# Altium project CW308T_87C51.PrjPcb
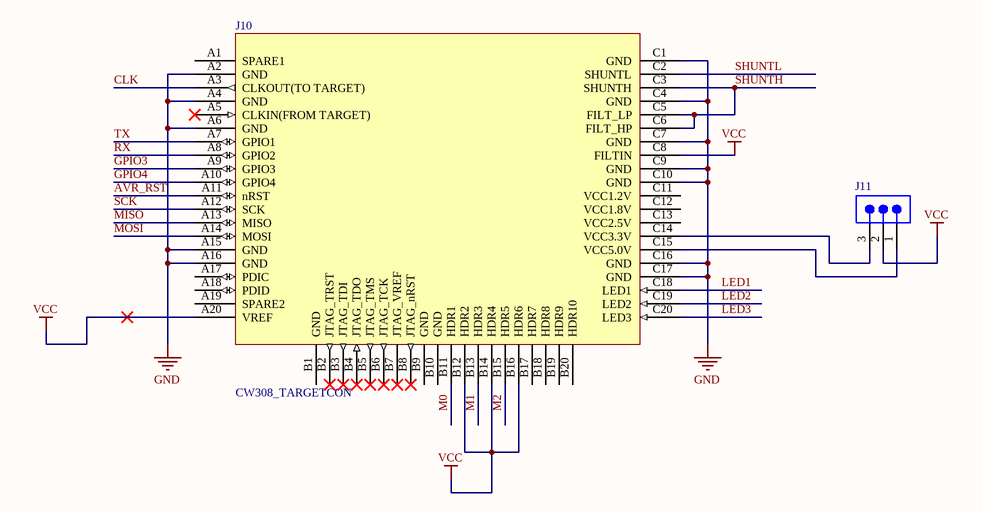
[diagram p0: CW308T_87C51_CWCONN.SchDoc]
2 sheets, 35 parts. Net scope: global (net labels, ports and power ports of the same name join across sheets).
Board file: CW308T_87C51.PcbDoc
Sheets:
  CW308T_87C51_CWCONN.SchDoc
  CW308T_87C51_CPU.SchDoc

## Sheet CW308T_87C51_CWCONN.SchDoc
size A4

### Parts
J10  CW308_TARGETCON  [CW308_TBOARD_CONN]
J11  68000-203HLF  [SMTC-TSW-103-07-X-S]  (value not drawn)

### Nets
GND: J10.A2(GND) J10.A4(GND) J10.A6(GND) J10.A15(GND) J10.A16(GND) J10.C1(GND) J10.C4(GND) J10.C7(GND) J10.C9(GND) J10.C10(GND) J10.C16(GND) J10.C17(GND)
VCC: J10.A20(VREF) J10.B12(HDR2) J10.B14(HDR4) J10.B16(HDR6) J10.C8(FILTIN) J11.2
AVR_RST: J10.A11(nRST)
CLK: J10.A3(CLKOUT(TO_TARGET))
GPIO3: J10.A9(GPIO3)
GPIO4: J10.A10(GPIO4)
LED1: J10.C18(LED1)
LED2: J10.C19(LED2)
LED3: J10.C20(LED3)
M0: J10.B11(HDR1)
M1: J10.B13(HDR3)
M2: J10.B15(HDR5)
MISO: J10.A13(MISO)
MOSI: J10.A14(MOSI)
RX: J10.A8(GPIO2)
SCK: J10.A12(SCK)
SHUNTH: J10.C3(SHUNTH) J10.C5(FILT_LP) J10.C6(FILT_HP)
SHUNTL: J10.C2(SHUNTL)
TX: J10.A7(GPIO1)
NetJ10_C14: J10.C14(VCC3.3V) J11.3
NetJ10_C15: J10.C15(VCC5.0V) J11.1

Not connected (* = marked no-connect by the designer): J10 A1(SPARE1) A5(CLKIN(FROM_TARGET))* A17(PDIC) A18(PDID) A19(SPARE2) B1(GND) B2(JTAG_TRST)* B3(JTAG_TDI)* B4(JTAG_TDO)* B5(JTAG_TMS)* B6(JTAG_TCK)* B7(JTAG_VREF)* B8(JTAG_nRST)* B9(GND) B10(GND) B17(HDR7) B18(HDR8) B19(HDR9) B20(HDR10) C11(VCC1.2V) C12(VCC1.8V) C13(VCC2.5V)

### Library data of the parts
J10 = CW308_TBOARD: CW308 "Standard" Target Board Connector
J11 = CMP-1024-00333-1: Manufacturer: Samtec; Pitch: 2.54 mm

## Sheet CW308T_87C51_CPU.SchDoc
size A4
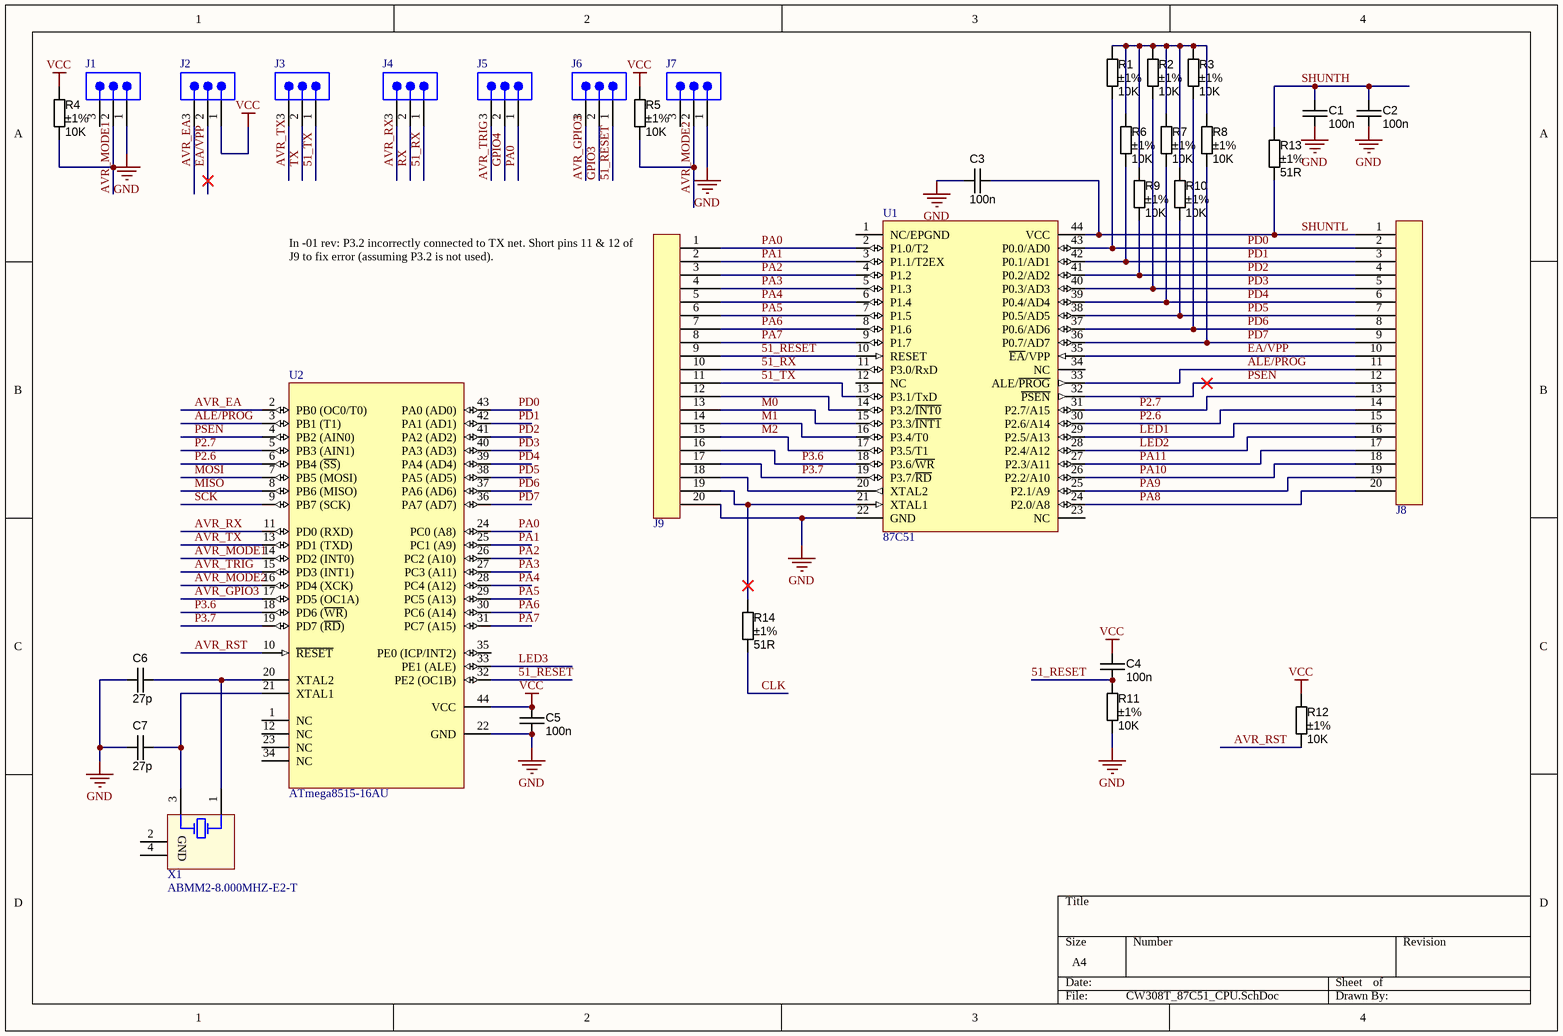
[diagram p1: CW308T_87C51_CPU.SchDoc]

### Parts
C1  value 100n  [CAPC1608X90N]  (hidden comment: approved sub OK)
C2  value 100n  [CAPC1608X90N]  (hidden comment: approved sub OK)
C3  value 100n  [CAPC1608X90N]  (hidden comment: approved sub OK)
C4  value 100n  [CAPC1608X90N]  (hidden comment: approved sub OK)
C5  value 100n  [CAPC1608X90N]  (hidden comment: approved sub OK)
C6  27p  [CAPC1608X90N]
C7  27p  [CAPC1608X90N]
J1  68000-203HLF  [SMTC-TSW-103-07-X-S]  (value not drawn)
J2  68000-203HLF  [SMTC-TSW-103-07-X-S]  (value not drawn)
J3  68000-203HLF  [SMTC-TSW-103-07-X-S]  (value not drawn)
J4  68000-203HLF  [SMTC-TSW-103-07-X-S]  (value not drawn)
J5  68000-203HLF  [SMTC-TSW-103-07-X-S]  (value not drawn)
J6  68000-203HLF  [SMTC-TSW-103-07-X-S]  (value not drawn)
J7  68000-203HLF  [SMTC-TSW-103-07-X-S]  (value not drawn)
J8  20-Pin Header  [801-87-020-10-001101]  (value not drawn)
J9  20-Pin Header  [801-87-020-10-001101]  (value not drawn)
R1  value 10K  Tolerance: ±1%  [RESC1608X55N]  (hidden comment: Thick Film)
R2  value 10K  Tolerance: ±1%  [RESC1608X55N]  (hidden comment: Thick Film)
R3  value 10K  Tolerance: ±1%  [RESC1608X55N]  (hidden comment: Thick Film)
R4  value 10K  Tolerance: ±1%  [RESC1608X55N]  (hidden comment: Thick Film)
R5  value 10K  Tolerance: ±1%  [RESC1608X55N]  (hidden comment: Thick Film)
R6  value 10K  Tolerance: ±1%  [RESC1608X55N]  (hidden comment: Thick Film)
R7  value 10K  Tolerance: ±1%  [RESC1608X55N]  (hidden comment: Thick Film)
R8  value 10K  Tolerance: ±1%  [RESC1608X55N]  (hidden comment: Thick Film)
R9  value 10K  Tolerance: ±1%  [RESC1608X55N]  (hidden comment: Thick Film)
R10  value 10K  Tolerance: ±1%  [RESC1608X55N]  (hidden comment: Thick Film)
R11  value 10K  Tolerance: ±1%  [RESC1608X55N]  (hidden comment: Thick Film)
R12  value 10K  Tolerance: ±1%  [RESC1608X55N]  (hidden comment: Thick Film)
R13  value 51R  Tolerance: ±1%  [RESC1608X55N]  (hidden comment: Thick Film)
R14  value 51R  Tolerance: ±1%  [RESC1608X55N]  (hidden comment: Thick Film)
U1  87C51  [PLCC44_SOCKET]
U2  ATmega8515-16AU  [44A_N]
X1  ABMM2-8.000MHZ-E2-T  [ABRA-ABMM2-4_V]

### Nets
GND: C1.2 C2.2 C3.1 C5.2 C6.1 C7.1 J1.1 J7.1 J9.20 R11.2 U1.22(GND) U2.22(GND)
VCC: C4.1 C5.1 J2.1 R4.1 R5.2 R12.1 U2.44(VCC)
51_RESET: C4.2 J6.1 J9.9 R11.1 U1.10(RESET) U2.32(PE2_(OC1B))
51_RX: J4.1 J9.10 U1.11(P3.0/RxD)
51_TX: J3.1 J9.11 U1.13(P3.1/TxD)
ALE/PROG: J8.11 U1.33(ALE/~{PROG}) U2.3(PB1_(T1))
AVR_EA: J2.3 U2.2(PB0_(OC0/T0))
AVR_GPIO3: J6.3 U2.17(PD5_(OC1A))
AVR_MODE1: J1.2 R4.2 U2.14(PD2_(INT0))
AVR_MODE2: J7.2 R5.1 U2.16(PD4_(XCK))
AVR_RST: R12.2 U2.10(~{RESET})
AVR_RX: J4.3 U2.11(PD0_(RXD))
AVR_TRIG: J5.3 U2.15(PD3_(INT1))
AVR_TX: J3.3 U2.13(PD1_(TXD))
CLK: R14.2
EA/VPP: J2.2 J8.10 U1.35(~{EA}/VPP)
GPIO3: J6.2
GPIO4: J5.2
LED1: J8.15 U1.29(P2.5/A13)
LED2: J8.16 U1.28(P2.4/A12)
LED3: U2.33(PE1_(ALE))
M0: J9.13 U1.15(P3.3/~{INT1})
M1: J9.14 U1.16(P3.4/T0)
M2: J9.15 U1.17(P3.5/T1)
MISO: U2.8(PB6_(MISO))
MOSI: U2.7(PB5_(MOSI))
P2.6: J8.14 U1.30(P2.6/A14) U2.6(PB4_(~{SS}))
P2.7: J8.13 U1.31(P2.7/A15) U2.5(PB3_(AIN1))
P3.6: J9.16 U1.18(P3.6/~{WR}) U2.18(PD6_(~{WR}))
P3.7: J9.17 U1.19(P3.7/~{RD}) U2.19(PD7_(~{RD}))
PA0: J5.1 J9.1 U1.2(P1.0/T2) U2.24(PC0_(A8))
PA1: J9.2 U1.3(P1.1/T2EX) U2.25(PC1_(A9))
PA2: J9.3 U1.4(P1.2) U2.26(PC2_(A10))
PA3: J9.4 U1.5(P1.3) U2.27(PC3_(A11))
PA4: J9.5 U1.6(P1.4) U2.28(PC4_(A12))
PA5: J9.6 U1.7(P1.5) U2.29(PC5_(A13))
PA6: J9.7 U1.8(P1.6) U2.30(PC6_(A14))
PA7: J9.8 U1.9(P1.7) U2.31(PC7_(A15))
PA8: J8.20 U1.24(P2.0/A8)
PA9: J8.19 U1.25(P2.1/A9)
PA10: J8.18 U1.26(P2.2/A10)
PA11: J8.17 U1.27(P2.3/A11)
PD0: J8.2 R1.2 U1.43(P0.0/AD0) U2.43(PA0_(AD0))
PD1: J8.3 R6.2 U1.42(P0.1/AD1) U2.42(PA1_(AD1))
PD2: J8.4 R9.2 U1.41(P0.2/AD2) U2.41(PA2_(AD2))
PD3: J8.5 R2.2 U1.40(P0.3/AD3) U2.40(PA3_(AD3))
PD4: J8.6 R7.2 U1.39(P0.4/AD4) U2.39(PA4_(AD4))
PD5: J8.7 R10.2 U1.38(P0.5/AD5) U2.38(PA5_(AD5))
PD6: J8.8 R3.2 U1.37(P0.6/AD6) U2.37(PA6_(AD6))
PD7: J8.9 R8.2 U1.36(P0.7/AD7) U2.36(PA7_(AD7))
PSEN: J8.12 U1.32(~{PSEN}) U2.4(PB2_(AIN0))
RX: J4.2
SCK: U2.9(PB7_(SCK))
SHUNTH: C1.1 C2.1 R13.1
SHUNTL: C3.2 J8.1 R13.2 U1.44(VCC)
TX: J3.2
NetC6_2: C6.2 U2.20(XTAL2) X1.1(X1)
NetC7_2: C7.2 U2.21(XTAL1) X1.3(X2)
NetJ9_12: J9.12 U1.14(P3.2/~{INT0})
NetJ9_18: J9.18 U1.20(XTAL2)
NetJ9_19: J9.19 R14.1 U1.21(XTAL1)
NetR1_1: R1.1 R2.1 R3.1 R6.1 R7.1 R8.1 R9.1 R10.1

Not connected (* = marked no-connect by the designer): J1 3; J7 3; U1 1(NC/EPGND) 12(NC) 23(NC) 34(NC); U2 1(NC) 12(NC) 23(NC) 34(NC) 35(PE0_(ICP/INT2)); X1 2(GND) 4(GND)

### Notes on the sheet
- (near J9) In -01 rev: P3.2 incorrectly connected to TX net. Short pins 11 & 12 of J9 to fix error (assuming P3.2 is not used).

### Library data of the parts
C1-C5 = CAPC_100n_0603_X7R_50V_10%: Capacitor SMD Cer 100nF 10% 50V X7R 0603; Manufacturer 1: AVX Corporation; Manufacturer Part Number 1: 06035C104KAT2A; Ratings: 50V; X7R; Material: ceramic; SCDType: spec
C6 C7 = CAPC_27p_0603_NP0_100V_1%: Capacitor SMD Cer 27pF 1% 100V NP0 0603; Manufacturer 1: AVX Corporation; Manufacturer Part Number 1: 06031A270FAT2A; Ratings: 100V; NP0; SCDType: undef
J1-J7 = CMP-1024-00333-1: Manufacturer: Samtec; Pitch: 2.54 mm
J8 J9 = 801-87-020-10-001101: 1x20 Header, Machined; Manufacture 1: Preci-Dip SA
R1-R12 = RES_10K_0603_1%: Resistor SMD chip 10k Ohm 0.1W 1% 0603; Manufacturer 1: Yageo; Manufacturer Part Number 1: RC0603FR-0710KL; Ratings: 1/10W; SCDType: spec
R13 R14 = RES_51R_0603_1%: Resistor SMD chip 51 Ohm 0.1W 1% 0603; Manufacturer 1: Yageo; Manufacturer Part Number 1: RC0603FR-0751RL; Ratings: 1/10 W; SCDType: spec
U2 = CMP-0095-00300-2: 8-bit AVR Microcontroller, 8KB Flash, 512 Bytes EEPROM, 512 Bytes SRAM, 4.5-5.5V, 44-pin TQFP, Industrial Grade (-40°C to 85°C)
X1 = CMP-0277-00003-1: Ceramic Surface Mount Low Profile Quartz Crystal, 8 MHz, -20 to 70 degC, 4-Pin 6 x 3.6 x 1.2 mm SMD, RoHS, 1000pcs / Reel; Manufacturer: Abracon; ESR: 72 Ohm Max.; Frequency: 8 MHz; Shunt Capacitance C0: 7 pF Max.; Load Capacitance CL: 18 pF Typ.

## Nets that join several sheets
GND: CW308T_87C51_CWCONN (12 pins), CW308T_87C51_CPU (12 pins)
VCC: CW308T_87C51_CWCONN (6 pins), CW308T_87C51_CPU (7 pins)
AVR_RST: CW308T_87C51_CWCONN (J10.A11), CW308T_87C51_CPU (R12.2 U2.10)
CLK: CW308T_87C51_CWCONN (J10.A3), CW308T_87C51_CPU (R14.2)
GPIO3: CW308T_87C51_CWCONN (J10.A9), CW308T_87C51_CPU (J6.2)
GPIO4: CW308T_87C51_CWCONN (J10.A10), CW308T_87C51_CPU (J5.2)
LED1: CW308T_87C51_CWCONN (J10.C18), CW308T_87C51_CPU (J8.15 U1.29)
LED2: CW308T_87C51_CWCONN (J10.C19), CW308T_87C51_CPU (J8.16 U1.28)
LED3: CW308T_87C51_CWCONN (J10.C20), CW308T_87C51_CPU (U2.33)
M0: CW308T_87C51_CWCONN (J10.B11), CW308T_87C51_CPU (J9.13 U1.15)
M1: CW308T_87C51_CWCONN (J10.B13), CW308T_87C51_CPU (J9.14 U1.16)
M2: CW308T_87C51_CWCONN (J10.B15), CW308T_87C51_CPU (J9.15 U1.17)
MISO: CW308T_87C51_CWCONN (J10.A13), CW308T_87C51_CPU (U2.8)
MOSI: CW308T_87C51_CWCONN (J10.A14), CW308T_87C51_CPU (U2.7)
RX: CW308T_87C51_CWCONN (J10.A8), CW308T_87C51_CPU (J4.2)
SCK: CW308T_87C51_CWCONN (J10.A12), CW308T_87C51_CPU (U2.9)
SHUNTH: CW308T_87C51_CWCONN (J10.C3 J10.C5 J10.C6), CW308T_87C51_CPU (C1.1 C2.1 R13.1)
SHUNTL: CW308T_87C51_CWCONN (J10.C2), CW308T_87C51_CPU (C3.2 J8.1 R13.2 U1.44)
TX: CW308T_87C51_CWCONN (J10.A7), CW308T_87C51_CPU (J3.2)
